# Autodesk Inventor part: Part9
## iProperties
Created: 2004-05
Part Number: Part9
Document SubType Name: Modeling
Designer: CADCIM Technologies
Manufacturer: Standard
Standards Organization: Custom
Author: CADCIM Technologies
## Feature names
1. Loft1
